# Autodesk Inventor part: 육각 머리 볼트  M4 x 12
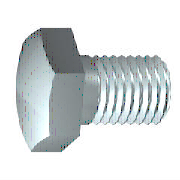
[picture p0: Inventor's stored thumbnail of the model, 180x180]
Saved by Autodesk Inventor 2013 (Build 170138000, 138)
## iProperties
IsCustomPart: 1
Created: 2012-02
Part Number: 육각 머리 볼트  M4 x 12
Material: 강철, 연강
Description: 6각 머리 나사
Document SubType Name: Modeling
Standard: ISO 4017
Designer: mdu-01
Standard Revision: Third edition 1999-08-15
Standards Organization: ISO
Language: ko-KR
Size Designation: M4 x 12
Categories: <MemberInstance><Categories><Category DisplayName="조임쇠" InternalName="e4da775c-781d-43d5-af7c-5136215cf5a6" Mnemonic="FSTN"><Category DisplayName="볼트" InternalN
Density: 7.75 g/cm^3
Author: mdu-01
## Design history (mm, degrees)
sketch "스케치1"
  geometry: L1 (0, 3.015)-(0, 2); L2 (2.1, 2)-(12, 2); L3 (12, 2)-(12, 0); L4 (12, 0)-(-0.4, 0); L5 (-2.88, 0)-(14.48, 0) reference; L6 (-0.4, 0)-(-0.4, 3.015); L7 (-0.4, 3.015)-(0, 3.015); L8 (2.1, 2)-(1.67, 2); L9 (1.67, 2)-(0, 2); L10 (0, -0.603)-(0, 3.618) reference
  constraints: 16 end point, 2 collinear, 2 perpendicular, 1 parallel
  dimensions: "d0" = 12 distance between parallel lines of L3 L1 (= NLG); "d1" = 9.9 distance from line of L2.start L3 (= GEL); "d2" = 4 diameter of L2 L4 (= GD); "d9" = 0.4001 distance between parallel lines of L6 L1 (computed from SD); "d10" = 6.03 diameter of L7 L4 (= SD2); "d13" = 0.42952 distance of L2.start L8.end (computed from GAL); "d14" = 4 diameter of L9 L4 (= BDM)
revolve "본체" sketch "스케치1" stored, may be unused: angle "d12" = 90 deg
sketch "스케치2"
  geometry: L1 (0, 4.041)-(3.5, 2.021); L2 (3.5, 2.021)-(3.5, -2.021); L3 (3.5, -2.021)-(0, -4.041); L4 (0, -4.041)-(-3.5, -2.021); L5 (-3.5, -2.021)-(-3.5, 2.021); L6 (-3.5, 2.021)-(0, 4.041); 2 further points
  constraints: 12 end point, 1 coincident, 1 vertical, 11 other
  dimensions: "d11" = 7 distance between parallel lines of L5 L2 (= SW)
extrude "머리" join sketch "스케치2" distance "d3" = 2.4 (= KOH - SD); taper "d4" = 0 deg
sketch "스케치4"
  geometry: L1 (-2.8, 3.5)-(-2.8, 4.041); L2 (-2.8, 4.041)-(-2.487, 4.041); L3 (-2.487, 4.041)-(-2.8, 3.5); L4 (-3.28, 0)-(0.08, 0) reference; L5 (-0.4, 4.041)-(-2.8, 4.041) reference; L6 (-2.8, 2.021)-(-2.8, 4.041) reference
  constraints: 6 end point, 2 collinear, 1 perpendicular, 1 vertical
  dimensions: "d5" = 30 deg angle of L3 L1 (= ANG1); "d19" = 7 diameter of L1.start L4 (= SW0)
revolve "모따기1" sketch "스케치4" stored, may be unused: angle "d21" = 90 deg
workplane "Work Plane1"
body "Solid1"
feature "스레드" dims "d15" = 9.9 (= GEL), "d16" = 0
chamfer "모따기2" distance "d6" = 0.42941 (= -0.5 x SPD + 0.5 x GD); stored, may be unused: second distance "d7" = 0.42952 (computed from GUL), angle "d55" = 45 deg
other parameters: "NLG" = 12 [user parameter; used in 1 equation term], "GD" = 4 (= NND) [user parameter; used in 2 equation terms], "BDM" = 4 (= NND) [user parameter; used in 1 equation term], "KOH" = 2.8 [user parameter; used in 1 equation term], "GEL" = 9.9 [user parameter; used in 2 equation terms], "SW" = 7 [user parameter; used in 2 equation terms], "SW0" = 7 (= SW) [user parameter; used in 1 equation term], "SPD" = 3.14117 (= NND - 1.2269 x PTC) [user parameter; used in 1 equation term], "SD2" = 6.03 [user parameter; used in 2 equation terms], "SD" = 0.4 [user parameter; used in 2 equation terms], "ANG1" = 30 deg [user parameter; used in 1 equation term], "GAL" = 0.42941 (= 0.61345 x PTC) [user parameter; used in 1 equation term], "GUL" = 0.42941 (= 0.61345 x PTC) [user parameter; used in 1 equation term], "d8" = 0, "RR" = 0.2 [user parameter], "d57" = 0, "d58" = 0, "TPU" = 14.28571 (computed from PTC) [user parameter], "GD1" = 3.14117 (= THREADDIA - 1.2269 x PTC) [user parameter], "THREADDIA" = 4 [user parameter; used in 1 equation term], "SDH" = 6.03 (= SD2) [user parameter], "SDHG" = 2.1 [user parameter], "TOA" = 30 deg [user parameter], "PTC" = 0.7 [user parameter; used in 5 equation terms], "NND" = 4 [user parameter; used in 3 equation terms], "E0" = 8.085 [user parameter]
